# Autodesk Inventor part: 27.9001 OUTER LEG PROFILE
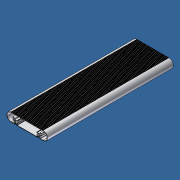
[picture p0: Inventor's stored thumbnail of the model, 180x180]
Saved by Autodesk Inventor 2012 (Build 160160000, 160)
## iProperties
Created: 2013-10
Part Number: 27.9001 OUTER LEG PROFILE
Material: Aluminum-6061
Document SubType Name: Modeling
Designer: Admin
Density: 2.71 g/cm^3
Mass: 2306.18 g
Surface Area: 6817.62 cm^2
Volume: 850.99 cm^3
Author: Admin
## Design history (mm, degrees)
node "H58-0011 OUTER ATU LEG_658-020011"
sketch "Sketch1"
  geometry: A1 r 5.9 centre (11.25, -18.75) between (7.366, -23.191) and (10.914, -24.64) reference; A2 r 5.9 centre (141.25, -18.75) between (145.134, -14.309) and (135.432, -17.772) reference; 16 further points
  constraints: 2 coincident
hole "M8 TAPS" sketch "Sketch1" at (11.25, -18.75), (141.25, -18.75) diameter "d0" = 7.647; stored, may be unused: countersink angle "d4" = 90 deg, drill point angle "d6" = 118 deg; dims "d1" = 30, "d2" = 4, "d3" = 2, "d5" = 35
node "Base1"
body "Solid1"
